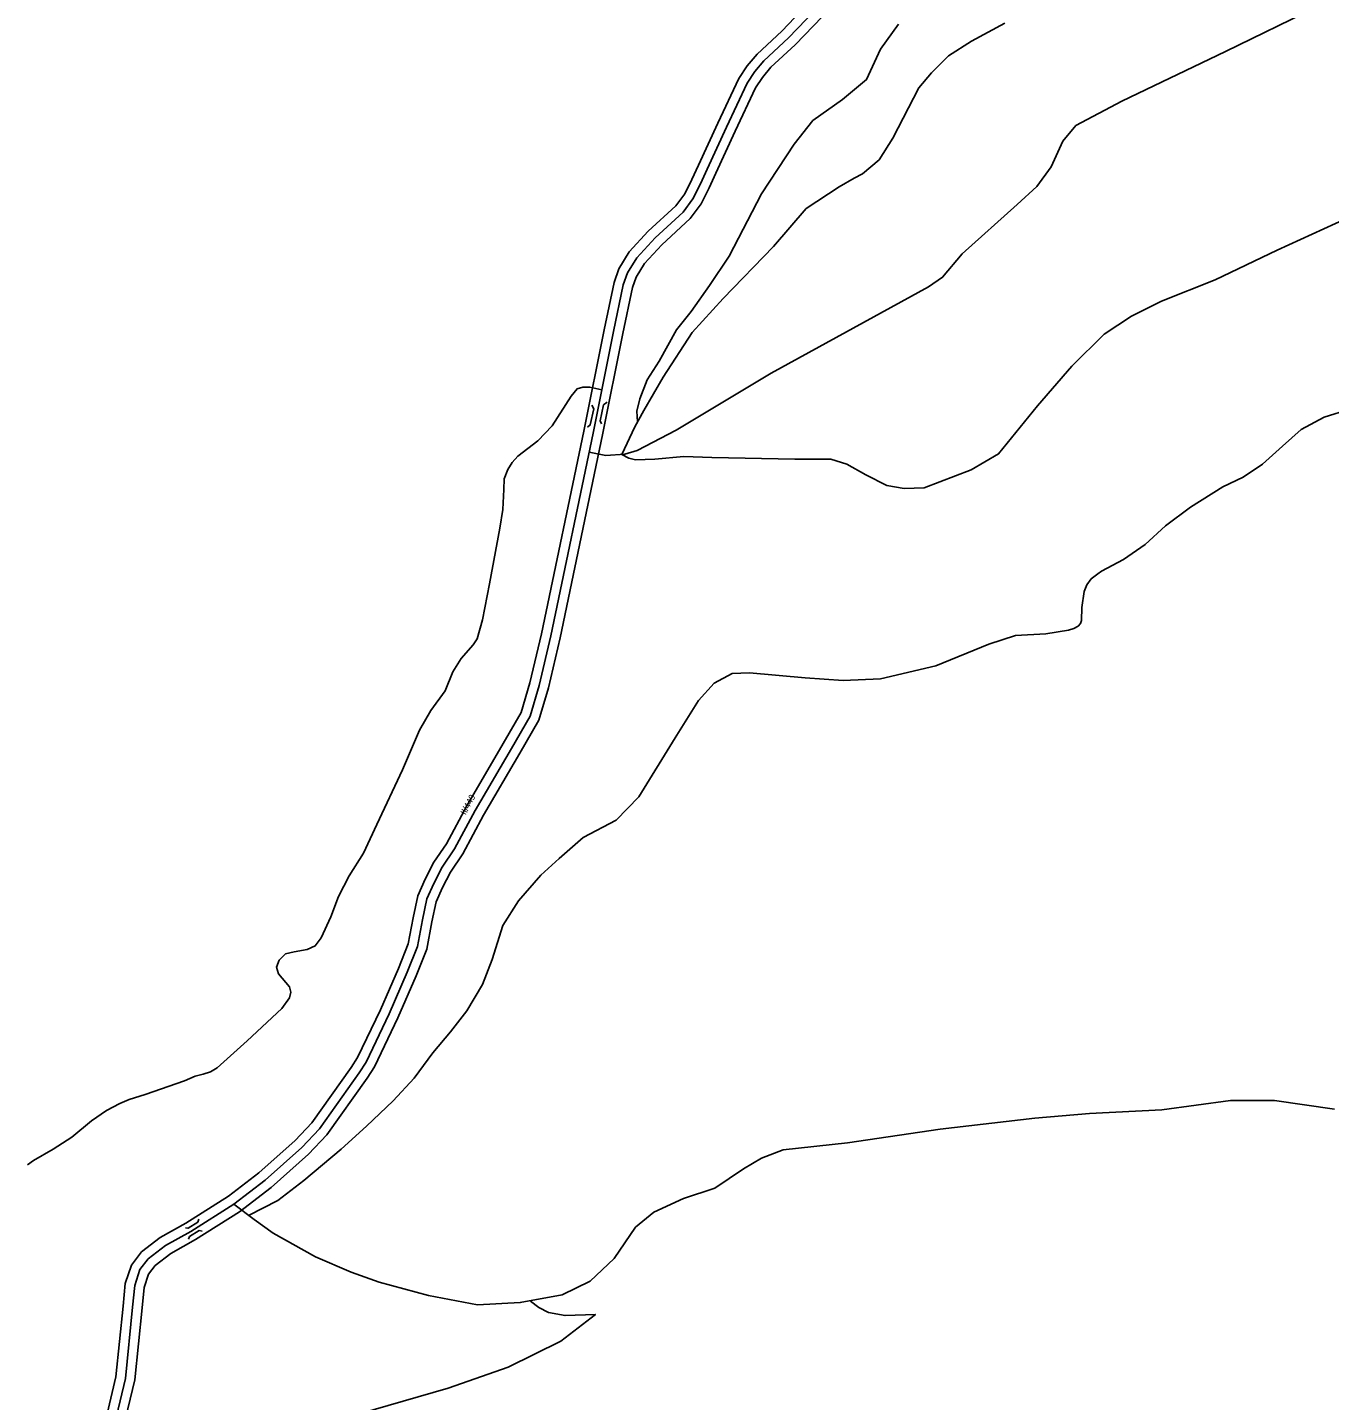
# Model space of a CAD drawing. Extents: x -547395 to -536032, y -1096268 to -1086572.
# Drawn here: x -546148 to -544105, y -1092255 to -1090100 of the extents above; entities that cross this region are included whole.
import ezdxf

# ---------------------------------------------------------------- set-up
doc = ezdxf.new("R2010")
doc.units = 0
for name, color, linetype in [('Vrstva 12', 7, 'Continuous'), ('Vrstva 5', 7, 'Continuous'), ('Vrstva 66', 7, 'Continuous'), ('Vrstva 75', 7, 'Continuous')]:
    doc.layers.add(name, color=color, linetype=linetype)

msp = doc.modelspace()

# ---------------------------------------------------------------- linework, layer by layer
at = {"layer": 'Vrstva 12'}
for points in [[(-544124.2, -1090067.5), (-544267.6, -1090137.6), (-544430.4, -1090215.4), (-544502.7, -1090253.6), (-544523, -1090278.1), (-544541.5, -1090318.2), (-544564.2, -1090349.3), (-544594.7, -1090377.4), (-544681, -1090454.8), (-544712, -1090491.8), (-544734.1, -1090506.8), (-544980.8, -1090642.5), (-545130.4, -1090731.9), (-545191.4, -1090763.5), (-545210.5, -1090769.5), (-545240.3, -1090771.3), (-545266.8, -1090766.5)], [(-544614, -1090092.8), (-544666.7, -1090121.1), (-544702.7, -1090144.2), (-544729.2, -1090170.8), (-544749, -1090194.6), (-544789.8, -1090273.5), (-544811.5, -1090307.5), (-544837.7, -1090329.6), (-544850.6, -1090336.4), (-544874.4, -1090350.1), (-544926.1, -1090384.1), (-544977.1, -1090443.3), (-545056.6, -1090524.9), (-545105.2, -1090578.3), (-545150.8, -1090648.4), (-545180.7, -1090700.8), (-545195, -1090726.7), (-545215.5, -1090769.8)], [(-545190.6, -1090718.7), (-545191.7, -1090701.7), (-545187.2, -1090682.8), (-545175.6, -1090652.8), (-545156.9, -1090623.2), (-545129.7, -1090574.2), (-545106.6, -1090545.7), (-545078, -1090504.8), (-545046.8, -1090458.6), (-544996.4, -1090360.6), (-544944.8, -1090283), (-544915.5, -1090245.6), (-544869.3, -1090212.9), (-544831.2, -1090181.6), (-544809.5, -1090134), (-544780.9, -1090094.5)], [(-545215.5, -1090769.8), (-545204.7, -1090775.9), (-545193.9, -1090778.3), (-545163.4, -1090777.1), (-545118.1, -1090773.2), (-545074.4, -1090774.4), (-544943.9, -1090777.1), (-544887.2, -1090777.1), (-544862.1, -1090784.9), (-544832.2, -1090801.6), (-544799.7, -1090818.7), (-544772.2, -1090823.5), (-544740.6, -1090822.3), (-544667.1, -1090794.2), (-544624.1, -1090769.1), (-544563.2, -1090693.7), (-544563.2, -1090693.7), (-544509.1, -1090631.3), (-544458.3, -1090581.1), (-544415.3, -1090553), (-544368.1, -1090529.1), (-544283.9, -1090495.6), (-544186.9, -1090449.2), (-544077, -1090399)], [(-545247, -1090668.4), (-545265.8, -1090664.2), (-545276.7, -1090664.2), (-545285.6, -1090667), (-545295.1, -1090678.5), (-545325, -1090724.8), (-545347.4, -1090748.6), (-545378.9, -1090772.3), (-545387.7, -1090782.5), (-545394.2, -1090793.4), (-545400.3, -1090808.3), (-545400.6, -1090825), (-545402, -1090856.3), (-545406.8, -1090885.6), (-545423.4, -1090973), (-545434.3, -1091029.5), (-545442.4, -1091059.4), (-545448.7, -1091068.4), (-545467.8, -1091090.2), (-545480.7, -1091110.9), (-545492.9, -1091140.9), (-545515.2, -1091171.7), (-545532.9, -1091202.3), (-545559.7, -1091264.9), (-545600, -1091350.5), (-545620.8, -1091395.4), (-545643.7, -1091430.9), (-545660.3, -1091463.6), (-545672.2, -1091495.6), (-545687.2, -1091528.6), (-545696.7, -1091540.8), (-545709.6, -1091546.6), (-545729.7, -1091550.3), (-545743.3, -1091553.7), (-545753.5, -1091563.3), (-545757.4, -1091574.7), (-545754.3, -1091585.2), (-545737, -1091605.3), (-545735, -1091613.8), (-545737.3, -1091622.6), (-545748.9, -1091639.3), (-545803.6, -1091690.3), (-545850.4, -1091732.4), (-545860.9, -1091738.8), (-545872.5, -1091742.6), (-545885.1, -1091745.6), (-545902.1, -1091753.1), (-545963.9, -1091774.2), (-545988.7, -1091782), (-546003.3, -1091788.5), (-546024.3, -1091799.2), (-546047.7, -1091815.5), (-546079, -1091841.4), (-546108.2, -1091860.1), (-546138.8, -1091878.1), (-546148.4, -1091884.5)], [(-544514.3, -1091045.6), (-544505.8, -1091043.1), (-544499.3, -1091039.3), (-544495.6, -1091035.3), (-544493.8, -1091030.5), (-544493.2, -1091010.1), (-544489.6, -1090985.1), (-544485.7, -1090974.7), (-544478.7, -1090965.3), (-544468, -1090957), (-544462.6, -1090952.9), (-544427.9, -1090934.5), (-544393.9, -1090911.4), (-544361.9, -1090882.1), (-544322.9, -1090852.6), (-544272.2, -1090820.6), (-544240.2, -1090805.3), (-544210, -1090785.2), (-544178.4, -1090756.6), (-544149, -1090730.6), (-544112.9, -1090711.5), (-544072.5, -1090698.9)], [(-545801.2, -1091964), (-545755.4, -1091940.8), (-545714.7, -1091909.5), (-545656.2, -1091859.9), (-545616.1, -1091823.8), (-545574.6, -1091784.3), (-545541.3, -1091748.9), (-545512.1, -1091708.8), (-545484.5, -1091675.8), (-545458.7, -1091643.1), (-545434.2, -1091601.6), (-545419.2, -1091562.2), (-545402.2, -1091509.1), (-545377.8, -1091470.3), (-545342.4, -1091430.1), (-545313.9, -1091403.7), (-545275.9, -1091371), (-545224.2, -1091343.8), (-545188.8, -1091307.1), (-545131.7, -1091214.5), (-545095, -1091156), (-545070.6, -1091128.8), (-545042, -1091113.8), (-545014.8, -1091112.5), (-544927.8, -1091120.6), (-544867.9, -1091124.7), (-544809.5, -1091122), (-544722.5, -1091101.6), (-544639.5, -1091067.6), (-544597.4, -1091054), (-544549.8, -1091051.2), (-544514.3, -1091045.6)], [(-545824.5, -1091946.4), (-545792.6, -1091970.5), (-545762.7, -1091991.9), (-545696.1, -1092029), (-545640.1, -1092053.4), (-545596.6, -1092068.7), (-545519, -1092089.7), (-545441.9, -1092104.6), (-545375, -1092101), (-545309.3, -1092088.5), (-545265.1, -1092067.5), (-545227.5, -1092031.7), (-545194.1, -1091982.7), (-545165.1, -1091959), (-545118.5, -1091937.5), (-545069.5, -1091921.4), (-545024.7, -1091890.9), (-544996.1, -1091874.2), (-544962, -1091861), (-544861.1, -1091850.2), (-544715.9, -1091828.7), (-544567.2, -1091811.4), (-544481.2, -1091804.2), (-544367.7, -1091798.2), (-544260.2, -1091783.9), (-544190.9, -1091783.9), (-544096.7, -1091797.2)], [(-545629.3, -1092275.9), (-545487.9, -1092235.1), (-545394.1, -1092202.4), (-545311.2, -1092161.6), (-545256.8, -1092119.4), (-545304.6, -1092121.3), (-545330.8, -1092116.6), (-545345.8, -1092108.8), (-545358.9, -1092098.6)]]:
    msp.add_lwpolyline(points, dxfattribs=at)
at = {"layer": 'Vrstva 5'}
msp.add_lwpolyline([(-544912.1, -1090072.7), (-544953.7, -1090116.2), (-544992.3, -1090151.9), (-545006.6, -1090169.1), (-545018.5, -1090187), (-545051.2, -1090256), (-545081.5, -1090322.1), (-545091.9, -1090345), (-545103.8, -1090368.8), (-545119.3, -1090389.6), (-545163.3, -1090430.1), (-545191.8, -1090461.1), (-545206.7, -1090484.9), (-545213.2, -1090503.9), (-545228.7, -1090577.1), (-545260.5, -1090736.3), (-545326.8, -1091054.4), (-545345.3, -1091132.4), (-545359.5, -1091180.6), (-545388.7, -1091231.2), (-545445.8, -1091328.8), (-545477.9, -1091388.9), (-545497.5, -1091417.5), (-545510.6, -1091443.1), (-545521.3, -1091467.5), (-545528.4, -1091500.2), (-545536.2, -1091541.9), (-545552.2, -1091582.3), (-545580.8, -1091647.8), (-545617, -1091723.4), (-545627.7, -1091740.1), (-545690.2, -1091828.1), (-545717.5, -1091857.3), (-545775.5, -1091908.8), (-545824.3, -1091946.3), (-545892.1, -1091989.1), (-545931.9, -1092011.1), (-545958.7, -1092032), (-545971.8, -1092049.2), (-545980.1, -1092074.2), (-545983.3, -1092107.9), (-545994.6, -1092219.8), (-546008.9, -1092279.3)], dxfattribs=at)
at = {"layer": 'Vrstva 66'}
for points in [[(-544923.4, -1090062.9), (-544964.2, -1090105.5), (-545003.2, -1090141.6), (-545018.7, -1090160.2), (-545031.6, -1090179.6), (-545064.8, -1090249.7), (-545095.2, -1090315.9), (-545105.5, -1090338.6), (-545116.7, -1090360.9), (-545130.5, -1090379.6), (-545173.9, -1090419.5), (-545203.8, -1090451.9), (-545220.3, -1090478.4), (-545227.7, -1090499.9), (-545243.4, -1090574.1), (-545275.2, -1090733.3), (-545341.5, -1091051.2), (-545359.8, -1091128.5), (-545373.4, -1091174.7), (-545401.6, -1091223.7), (-545458.9, -1091321.5), (-545490.7, -1091381.1), (-545510.4, -1091409.8), (-545524.1, -1091436.6), (-545535.6, -1091462.8), (-545543.1, -1091497.2), (-545550.6, -1091537.7), (-545566.1, -1091576.6), (-545594.4, -1091641.6), (-545630.2, -1091716.1), (-545640.2, -1091731.7), (-545701.8, -1091818.6), (-545728, -1091846.5), (-545785.1, -1091897.2), (-545832.9, -1091934), (-545899.7, -1091976.2), (-545940.2, -1091998.6), (-545969.4, -1092021.4), (-545985.2, -1092042.2), (-545994.8, -1092071.1), (-545998.3, -1092106.4), (-546009.5, -1092217.2), (-546023.5, -1092275.6)], [(-545994.4, -1092282.9), (-545979.8, -1092222.3), (-545968.4, -1092109.3), (-545965.3, -1092077.4), (-545958.3, -1092056.3), (-545947.9, -1092042.6), (-545923.6, -1092023.7), (-545884.4, -1092002), (-545815.7, -1091958.6), (-545765.9, -1091920.3), (-545707.1, -1091868.1), (-545678.5, -1091837.7), (-545615.3, -1091748.5), (-545603.9, -1091730.7), (-545567.1, -1091654.1), (-545538.4, -1091588.1), (-545521.7, -1091546), (-545513.7, -1091503.2), (-545507, -1091472.1), (-545497, -1091449.5), (-545484.6, -1091425.2), (-545465, -1091396.7), (-545432.7, -1091336.1), (-545375.7, -1091238.7), (-545345.7, -1091186.6), (-545330.8, -1091136.3), (-545312.2, -1091057.7), (-545245.8, -1090739.3), (-545214, -1090580.1), (-545198.8, -1090507.9), (-545193.1, -1090491.4), (-545179.9, -1090470.2), (-545152.7, -1090440.7), (-545108.1, -1090399.7), (-545091, -1090376.7), (-545078.4, -1090351.5), (-545067.9, -1090328.3), (-545037.6, -1090262.4), (-545005.4, -1090194.4), (-544994.5, -1090178.1), (-544981.4, -1090162.2), (-544943.2, -1090126.9), (-544900.7, -1090082.6)]]:
    msp.add_lwpolyline(points, dxfattribs=at)
at = {"layer": 'Vrstva 75'}
for points in [[(-545262.6, -1090692.4), (-545259.5, -1090698.5), (-545265, -1090723.4), (-545269.4, -1090726.9)], [(-545238.7, -1090687.8), (-545244.1, -1090692), (-545249.6, -1090716.9), (-545247.1, -1090721.9)], [(-545879.3, -1091970.2), (-545880.8, -1091974.6), (-545896.2, -1091984.1), (-545900.3, -1091983.4)], [(-545874.3, -1091988.7), (-545878.9, -1091988), (-545894.3, -1091997.4), (-545895.5, -1092001.5)]]:
    msp.add_lwpolyline(points, dxfattribs=at)

# ---------------------------------------------------------------- texts
at = {"layer": 'Vrstva 5'}
msp.add_text('II/449', height=10, rotation=61.8894, dxfattribs=at).set_placement((-545460.6, -1091336.4))

doc.saveas('drawing.dxf')
